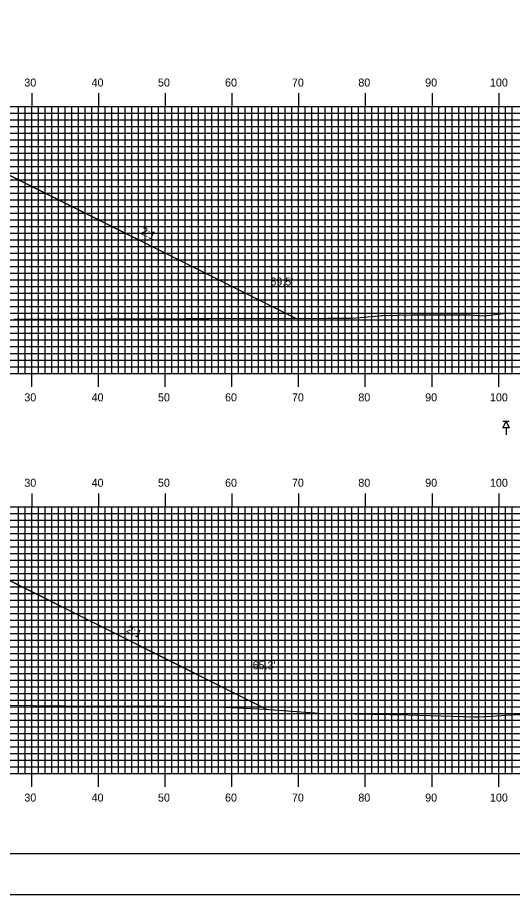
# Model space of a CAD drawing. Extents: x 1809013 to 1809356, y 442591 to 442811.
# Drawn here: x 1809206.2 to 1809280.4, y 442590.5 to 442722 of the extents above; entities that cross this region are included whole.
import ezdxf

# ---------------------------------------------------------------- set-up
doc = ezdxf.new("R2010")
doc.units = 0
for name, color, linetype in [('ANNOTATION', 7, 'Continuous'), ('BORDER', 7, 'Continuous'), ('BORING - NO REFUSAL', 7, 'Continuous'), ('D_Roadway_Centerline', 7, 'Continuous'), ('D_Roadway_SlopeLines', 7, 'Continuous'), ('D_Text_Standard', 7, 'Continuous'), ('H_V ANNOTATION', 7, 'Continuous'), ('MAJOR', 7, 'Continuous'), ('MINOR', 7, 'Continuous'), ('PLOT BOUNDARY', 7, 'Continuous'), ('S_Roadway_Centerline', 7, 'Continuous')]:
    doc.layers.add(name, color=color, linetype=linetype)

msp = doc.modelspace()

# ---------------------------------------------------------------- linework, layer by layer
at = {"layer": 'BORDER'}
msp.add_lwpolyline([(1809028.72, 442596.67), (1809348.72, 442596.67), (1809348.72, 442806.67), (1809028.72, 442806.67)], close=True, dxfattribs=at)
at = {"layer": 'BORING - NO REFUSAL'}
for p, q in [((1809279.9, 442661.47), (1809278.94, 442661.47)), ((1809279.42, 442660.51), (1809279.42, 442659.45))]:
    msp.add_line(p, q, dxfattribs=at)
msp.add_lwpolyline([(1809279.42, 442661.47), (1809279.9, 442660.51), (1809278.94, 442660.51)], close=True, dxfattribs=at)
at = {"layer": 'D_Roadway_Centerline'}
for points in [[(1809112.65, 442678.85), (1809150.57, 442697.82), (1809155.32, 442700.19), (1809158.32, 442700.31), (1809166.32, 442700.63), (1809178.32, 442700.87), (1809190.32, 442700.63), (1809198.32, 442700.31), (1809201.32, 442700.19), (1809206.07, 442697.82), (1809247.86, 442676.92)], [(1809117.27, 442620.41), (1809150.57, 442637.07), (1809155.32, 442639.44), (1809158.32, 442639.56), (1809166.32, 442639.88), (1809178.32, 442640.12), (1809190.32, 442639.88), (1809198.32, 442639.56), (1809201.32, 442639.44), (1809206.07, 442637.07), (1809243.63, 442618.29)]]:
    msp.add_lwpolyline(points, dxfattribs=at)
at = {"layer": 'D_Roadway_SlopeLines'}
for points in [[(1809201.32, 442700.19), (1809247.86, 442676.92)], [(1809201.32, 442639.44), (1809243.63, 442618.29)]]:
    msp.add_lwpolyline(points, dxfattribs=at)
at = {"layer": 'MAJOR'}
for p, q in [((1809208.32, 442710.67), (1809208.32, 442708.67)), ((1809218.32, 442710.67), (1809218.32, 442708.67)), ((1809228.32, 442710.67), (1809228.32, 442708.67)), ((1809238.32, 442710.67), (1809238.32, 442708.67)), ((1809248.32, 442710.67), (1809248.32, 442708.67)), ((1809258.32, 442710.67), (1809258.32, 442708.67)), ((1809268.32, 442710.67), (1809268.32, 442708.67)), ((1809278.32, 442710.67), (1809278.32, 442708.67)), ((1809038.32, 442708.67), (1809318.32, 442708.67)), ((1809038.32, 442708.67), (1809318.32, 442708.67)), ((1809208.32, 442668.67), (1809208.32, 442708.67)), ((1809218.32, 442668.67), (1809218.32, 442708.67)), ((1809228.32, 442668.67), (1809228.32, 442708.67)), ((1809238.32, 442668.67), (1809238.32, 442708.67)), ((1809248.32, 442668.67), (1809248.32, 442708.67)), ((1809258.32, 442668.67), (1809258.32, 442708.67)), ((1809268.32, 442668.67), (1809268.32, 442708.67)), ((1809278.32, 442668.67), (1809278.32, 442708.67)), ((1809038.32, 442703.67), (1809318.32, 442703.67)), ((1809038.32, 442698.67), (1809318.32, 442698.67)), ((1809038.32, 442693.67), (1809318.32, 442693.67)), ((1809038.32, 442688.67), (1809318.32, 442688.67)), ((1809038.32, 442683.67), (1809318.32, 442683.67)), ((1809038.32, 442678.67), (1809318.32, 442678.67)), ((1809038.32, 442673.67), (1809318.32, 442673.67)), ((1809038.32, 442668.67), (1809318.32, 442668.67)), ((1809038.32, 442668.67), (1809318.32, 442668.67)), ((1809208.32, 442666.66), (1809208.32, 442668.67)), ((1809218.32, 442666.66), (1809218.32, 442668.67)), ((1809228.32, 442666.66), (1809228.32, 442668.67)), ((1809238.32, 442666.66), (1809238.32, 442668.67)), ((1809248.32, 442666.66), (1809248.32, 442668.67)), ((1809258.32, 442666.66), (1809258.32, 442668.67)), ((1809268.32, 442666.66), (1809268.32, 442668.67)), ((1809278.32, 442666.66), (1809278.32, 442668.67)), ((1809208.32, 442650.67), (1809208.32, 442648.67)), ((1809218.32, 442650.67), (1809218.32, 442648.67)), ((1809228.32, 442650.67), (1809228.32, 442648.67)), ((1809238.32, 442650.67), (1809238.32, 442648.67)), ((1809248.32, 442650.67), (1809248.32, 442648.67)), ((1809258.32, 442650.67), (1809258.32, 442648.67)), ((1809268.32, 442650.67), (1809268.32, 442648.67)), ((1809278.32, 442650.67), (1809278.32, 442648.67)), ((1809038.32, 442648.67), (1809318.32, 442648.67)), ((1809038.32, 442648.67), (1809318.32, 442648.67)), ((1809208.32, 442608.67), (1809208.32, 442648.67)), ((1809218.32, 442608.67), (1809218.32, 442648.67)), ((1809228.32, 442608.67), (1809228.32, 442648.67)), ((1809238.32, 442608.67), (1809238.32, 442648.67)), ((1809248.32, 442608.67), (1809248.32, 442648.67)), ((1809258.32, 442608.67), (1809258.32, 442648.67)), ((1809268.32, 442608.67), (1809268.32, 442648.67)), ((1809278.32, 442608.67), (1809278.32, 442648.67)), ((1809038.32, 442643.67), (1809318.32, 442643.67)), ((1809038.32, 442638.67), (1809318.32, 442638.67)), ((1809038.32, 442633.67), (1809318.32, 442633.67)), ((1809038.32, 442628.67), (1809318.32, 442628.67)), ((1809038.32, 442623.67), (1809318.32, 442623.67)), ((1809038.32, 442618.67), (1809318.32, 442618.67)), ((1809038.32, 442613.67), (1809318.32, 442613.67)), ((1809038.32, 442608.67), (1809318.32, 442608.67)), ((1809038.32, 442608.67), (1809318.32, 442608.67)), ((1809208.32, 442606.66), (1809208.32, 442608.67)), ((1809218.32, 442606.66), (1809218.32, 442608.67)), ((1809228.32, 442606.66), (1809228.32, 442608.67)), ((1809238.32, 442606.66), (1809238.32, 442608.67)), ((1809248.32, 442606.66), (1809248.32, 442608.67)), ((1809258.32, 442606.66), (1809258.32, 442608.67)), ((1809268.32, 442606.66), (1809268.32, 442608.67)), ((1809278.32, 442606.66), (1809278.32, 442608.67))]:
    msp.add_line(p, q, dxfattribs=at)
at = {"layer": 'MINOR'}
for p, q in [((1809206.32, 442668.67), (1809206.32, 442708.67)), ((1809207.32, 442668.67), (1809207.32, 442708.67)), ((1809209.32, 442668.67), (1809209.32, 442708.67)), ((1809210.32, 442668.67), (1809210.32, 442708.67)), ((1809211.32, 442668.67), (1809211.32, 442708.67)), ((1809212.32, 442668.67), (1809212.32, 442708.67)), ((1809213.32, 442668.67), (1809213.32, 442708.67)), ((1809214.32, 442668.67), (1809214.32, 442708.67)), ((1809215.32, 442668.67), (1809215.32, 442708.67)), ((1809216.32, 442668.67), (1809216.32, 442708.67)), ((1809217.32, 442668.67), (1809217.32, 442708.67)), ((1809219.32, 442668.67), (1809219.32, 442708.67)), ((1809220.32, 442668.67), (1809220.32, 442708.67)), ((1809221.32, 442668.67), (1809221.32, 442708.67)), ((1809222.32, 442668.67), (1809222.32, 442708.67)), ((1809223.32, 442668.67), (1809223.32, 442708.67)), ((1809224.32, 442668.67), (1809224.32, 442708.67)), ((1809225.32, 442668.67), (1809225.32, 442708.67)), ((1809226.32, 442668.67), (1809226.32, 442708.67)), ((1809227.32, 442668.67), (1809227.32, 442708.67)), ((1809229.32, 442668.67), (1809229.32, 442708.67)), ((1809230.32, 442668.67), (1809230.32, 442708.67)), ((1809231.32, 442668.67), (1809231.32, 442708.67)), ((1809232.32, 442668.67), (1809232.32, 442708.67)), ((1809233.32, 442668.67), (1809233.32, 442708.67)), ((1809234.32, 442668.67), (1809234.32, 442708.67)), ((1809235.32, 442668.67), (1809235.32, 442708.67)), ((1809236.32, 442668.67), (1809236.32, 442708.67)), ((1809237.32, 442668.67), (1809237.32, 442708.67)), ((1809239.32, 442668.67), (1809239.32, 442708.67)), ((1809240.32, 442668.67), (1809240.32, 442708.67)), ((1809241.32, 442668.67), (1809241.32, 442708.67)), ((1809242.32, 442668.67), (1809242.32, 442708.67)), ((1809243.32, 442668.67), (1809243.32, 442708.67)), ((1809244.32, 442668.67), (1809244.32, 442708.67)), ((1809245.32, 442668.67), (1809245.32, 442708.67)), ((1809246.32, 442668.67), (1809246.32, 442708.67)), ((1809247.32, 442668.67), (1809247.32, 442708.67)), ((1809249.32, 442668.67), (1809249.32, 442708.67)), ((1809250.32, 442668.67), (1809250.32, 442708.67)), ((1809251.32, 442668.67), (1809251.32, 442708.67)), ((1809252.32, 442668.67), (1809252.32, 442708.67)), ((1809253.32, 442668.67), (1809253.32, 442708.67)), ((1809254.32, 442668.67), (1809254.32, 442708.67)), ((1809255.32, 442668.67), (1809255.32, 442708.67)), ((1809256.32, 442668.67), (1809256.32, 442708.67)), ((1809257.32, 442668.67), (1809257.32, 442708.67)), ((1809259.32, 442668.67), (1809259.32, 442708.67)), ((1809260.32, 442668.67), (1809260.32, 442708.67)), ((1809261.32, 442668.67), (1809261.32, 442708.67)), ((1809262.32, 442668.67), (1809262.32, 442708.67)), ((1809263.32, 442668.67), (1809263.32, 442708.67)), ((1809264.32, 442668.67), (1809264.32, 442708.67)), ((1809265.32, 442668.67), (1809265.32, 442708.67)), ((1809266.32, 442668.67), (1809266.32, 442708.67)), ((1809267.32, 442668.67), (1809267.32, 442708.67)), ((1809269.32, 442668.67), (1809269.32, 442708.67)), ((1809270.32, 442668.67), (1809270.32, 442708.67)), ((1809271.32, 442668.67), (1809271.32, 442708.67)), ((1809272.32, 442668.67), (1809272.32, 442708.67)), ((1809273.32, 442668.67), (1809273.32, 442708.67)), ((1809274.32, 442668.67), (1809274.32, 442708.67)), ((1809275.32, 442668.67), (1809275.32, 442708.67)), ((1809276.32, 442668.67), (1809276.32, 442708.67)), ((1809277.32, 442668.67), (1809277.32, 442708.67)), ((1809279.32, 442668.67), (1809279.32, 442708.67)), ((1809280.32, 442668.67), (1809280.32, 442708.67)), ((1809038.32, 442707.67), (1809318.32, 442707.67)), ((1809038.32, 442706.67), (1809318.32, 442706.67)), ((1809038.32, 442705.67), (1809318.32, 442705.67)), ((1809038.32, 442704.67), (1809318.32, 442704.67)), ((1809038.32, 442702.67), (1809318.32, 442702.67)), ((1809038.32, 442701.67), (1809318.32, 442701.67)), ((1809038.32, 442700.67), (1809318.32, 442700.67)), ((1809038.32, 442699.67), (1809318.32, 442699.67)), ((1809038.32, 442697.67), (1809318.32, 442697.67)), ((1809038.32, 442696.67), (1809318.32, 442696.67)), ((1809038.32, 442695.67), (1809318.32, 442695.67)), ((1809038.32, 442694.67), (1809318.32, 442694.67)), ((1809038.32, 442692.67), (1809318.32, 442692.67)), ((1809038.32, 442691.67), (1809318.32, 442691.67)), ((1809038.32, 442690.67), (1809318.32, 442690.67)), ((1809038.32, 442689.67), (1809318.32, 442689.67)), ((1809038.32, 442687.67), (1809318.32, 442687.67)), ((1809038.32, 442686.67), (1809318.32, 442686.67)), ((1809038.32, 442685.67), (1809318.32, 442685.67)), ((1809038.32, 442684.67), (1809318.32, 442684.67)), ((1809038.32, 442682.67), (1809318.32, 442682.67)), ((1809038.32, 442681.67), (1809318.32, 442681.67)), ((1809038.32, 442680.67), (1809318.32, 442680.67)), ((1809038.32, 442679.67), (1809318.32, 442679.67)), ((1809038.32, 442677.67), (1809318.32, 442677.67)), ((1809038.32, 442676.67), (1809318.32, 442676.67)), ((1809038.32, 442675.67), (1809318.32, 442675.67)), ((1809038.32, 442674.67), (1809318.32, 442674.67)), ((1809038.32, 442672.67), (1809318.32, 442672.67)), ((1809038.32, 442671.67), (1809318.32, 442671.67)), ((1809038.32, 442670.67), (1809318.32, 442670.67)), ((1809038.32, 442669.67), (1809318.32, 442669.67)), ((1809038.32, 442647.67), (1809318.32, 442647.67)), ((1809206.32, 442608.67), (1809206.32, 442648.67)), ((1809207.32, 442608.67), (1809207.32, 442648.67)), ((1809209.32, 442608.67), (1809209.32, 442648.67)), ((1809210.32, 442608.67), (1809210.32, 442648.67)), ((1809211.32, 442608.67), (1809211.32, 442648.67)), ((1809212.32, 442608.67), (1809212.32, 442648.67)), ((1809213.32, 442608.67), (1809213.32, 442648.67)), ((1809214.32, 442608.67), (1809214.32, 442648.67)), ((1809215.32, 442608.67), (1809215.32, 442648.67)), ((1809216.32, 442608.67), (1809216.32, 442648.67)), ((1809217.32, 442608.67), (1809217.32, 442648.67)), ((1809219.32, 442608.67), (1809219.32, 442648.67)), ((1809220.32, 442608.67), (1809220.32, 442648.67)), ((1809221.32, 442608.67), (1809221.32, 442648.67)), ((1809222.32, 442608.67), (1809222.32, 442648.67)), ((1809223.32, 442608.67), (1809223.32, 442648.67)), ((1809224.32, 442608.67), (1809224.32, 442648.67)), ((1809225.32, 442608.67), (1809225.32, 442648.67)), ((1809226.32, 442608.67), (1809226.32, 442648.67)), ((1809227.32, 442608.67), (1809227.32, 442648.67)), ((1809229.32, 442608.67), (1809229.32, 442648.67)), ((1809230.32, 442608.67), (1809230.32, 442648.67)), ((1809231.32, 442608.67), (1809231.32, 442648.67)), ((1809232.32, 442608.67), (1809232.32, 442648.67)), ((1809233.32, 442608.67), (1809233.32, 442648.67)), ((1809234.32, 442608.67), (1809234.32, 442648.67)), ((1809235.32, 442608.67), (1809235.32, 442648.67)), ((1809236.32, 442608.67), (1809236.32, 442648.67)), ((1809237.32, 442608.67), (1809237.32, 442648.67)), ((1809239.32, 442608.67), (1809239.32, 442648.67)), ((1809240.32, 442608.67), (1809240.32, 442648.67)), ((1809241.32, 442608.67), (1809241.32, 442648.67)), ((1809242.32, 442608.67), (1809242.32, 442648.67)), ((1809243.32, 442608.67), (1809243.32, 442648.67)), ((1809244.32, 442608.67), (1809244.32, 442648.67)), ((1809245.32, 442608.67), (1809245.32, 442648.67)), ((1809246.32, 442608.67), (1809246.32, 442648.67)), ((1809247.32, 442608.67), (1809247.32, 442648.67)), ((1809249.32, 442608.67), (1809249.32, 442648.67)), ((1809250.32, 442608.67), (1809250.32, 442648.67)), ((1809251.32, 442608.67), (1809251.32, 442648.67)), ((1809252.32, 442608.67), (1809252.32, 442648.67)), ((1809253.32, 442608.67), (1809253.32, 442648.67)), ((1809254.32, 442608.67), (1809254.32, 442648.67)), ((1809255.32, 442608.67), (1809255.32, 442648.67)), ((1809256.32, 442608.67), (1809256.32, 442648.67)), ((1809257.32, 442608.67), (1809257.32, 442648.67)), ((1809259.32, 442608.67), (1809259.32, 442648.67)), ((1809260.32, 442608.67), (1809260.32, 442648.67)), ((1809261.32, 442608.67), (1809261.32, 442648.67)), ((1809262.32, 442608.67), (1809262.32, 442648.67)), ((1809263.32, 442608.67), (1809263.32, 442648.67)), ((1809264.32, 442608.67), (1809264.32, 442648.67)), ((1809265.32, 442608.67), (1809265.32, 442648.67)), ((1809266.32, 442608.67), (1809266.32, 442648.67)), ((1809267.32, 442608.67), (1809267.32, 442648.67)), ((1809269.32, 442608.67), (1809269.32, 442648.67)), ((1809270.32, 442608.67), (1809270.32, 442648.67)), ((1809271.32, 442608.67), (1809271.32, 442648.67)), ((1809272.32, 442608.67), (1809272.32, 442648.67)), ((1809273.32, 442608.67), (1809273.32, 442648.67)), ((1809274.32, 442608.67), (1809274.32, 442648.67)), ((1809275.32, 442608.67), (1809275.32, 442648.67)), ((1809276.32, 442608.67), (1809276.32, 442648.67)), ((1809277.32, 442608.67), (1809277.32, 442648.67)), ((1809279.32, 442608.67), (1809279.32, 442648.67)), ((1809280.32, 442608.67), (1809280.32, 442648.67)), ((1809038.32, 442646.67), (1809318.32, 442646.67)), ((1809038.32, 442645.67), (1809318.32, 442645.67)), ((1809038.32, 442644.67), (1809318.32, 442644.67)), ((1809038.32, 442642.67), (1809318.32, 442642.67)), ((1809038.32, 442641.67), (1809318.32, 442641.67)), ((1809038.32, 442640.67), (1809318.32, 442640.67)), ((1809038.32, 442639.67), (1809318.32, 442639.67)), ((1809038.32, 442637.67), (1809318.32, 442637.67)), ((1809038.32, 442636.67), (1809318.32, 442636.67)), ((1809038.32, 442635.67), (1809318.32, 442635.67)), ((1809038.32, 442634.67), (1809318.32, 442634.67)), ((1809038.32, 442632.67), (1809318.32, 442632.67)), ((1809038.32, 442631.67), (1809318.32, 442631.67)), ((1809038.32, 442630.67), (1809318.32, 442630.67)), ((1809038.32, 442629.67), (1809318.32, 442629.67)), ((1809038.32, 442627.67), (1809318.32, 442627.67)), ((1809038.32, 442626.67), (1809318.32, 442626.67)), ((1809038.32, 442625.67), (1809318.32, 442625.67)), ((1809038.32, 442624.67), (1809318.32, 442624.67)), ((1809038.32, 442622.67), (1809318.32, 442622.67)), ((1809038.32, 442621.67), (1809318.32, 442621.67)), ((1809038.32, 442620.67), (1809318.32, 442620.67)), ((1809038.32, 442619.67), (1809318.32, 442619.67)), ((1809038.32, 442617.67), (1809318.32, 442617.67)), ((1809038.32, 442616.67), (1809318.32, 442616.67)), ((1809038.32, 442615.67), (1809318.32, 442615.67)), ((1809038.32, 442614.67), (1809318.32, 442614.67)), ((1809038.32, 442612.67), (1809318.32, 442612.67)), ((1809038.32, 442611.67), (1809318.32, 442611.67)), ((1809038.32, 442610.67), (1809318.32, 442610.67)), ((1809038.32, 442609.67), (1809318.32, 442609.67))]:
    msp.add_line(p, q, dxfattribs=at)
at = {"layer": 'PLOT BOUNDARY'}
msp.add_lwpolyline([(1809012.54, 442590.55), (1809352.54, 442590.55), (1809352.54, 442810.55), (1809012.54, 442810.55)], close=True, dxfattribs=at)
at = {"layer": 'S_Roadway_Centerline'}
for points in [[(1809205.65, 442676.78), (1809207.67, 442676.78), (1809219.35, 442676.83), (1809222.57, 442676.83), (1809231.48, 442676.89), (1809234.9, 442676.9), (1809252.73, 442676.93), (1809252.96, 442676.93), (1809253.24, 442676.93), (1809256.39, 442676.94), (1809260.9, 442677.36), (1809265.23, 442677.45), (1809274.04, 442677.45), (1809276.16, 442677.27), (1809279.43, 442677.68), (1809289.04, 442677.69), (1809293.8, 442677.99), (1809300.57, 442678.12), (1809308.92, 442678), (1809318.32, 442678.09)], [(1809193.97, 442619.02), (1809218.3, 442618.76), (1809228.11, 442618.77), (1809236.02, 442618.69), (1809243.32, 442618.31), (1809251.38, 442617.73), (1809264.7, 442617.5), (1809274.69, 442617.17), (1809275.36, 442617.17), (1809276.46, 442617.23), (1809280.18, 442617.49), (1809282.88, 442617.51), (1809283.8, 442617.55), (1809291.27, 442617.59), (1809303.06, 442617.71), (1809308.91, 442617.68), (1809309.81, 442617.36), (1809313.26, 442616.98), (1809314.08, 442617.1), (1809318.32, 442617.11)]]:
    msp.add_lwpolyline(points, dxfattribs=at)

# ---------------------------------------------------------------- texts
at = {"layer": 'ANNOTATION'}
for p in [(1809224.53, 442689.63), (1809222.41, 442629.93)]:
    msp.add_text('2:1', height=1.2, rotation=333.4349, dxfattribs=at).set_placement(p)
at = {"layer": 'D_Text_Standard'}
for s, p in [("69.5'", (1809244.1, 442681.83)), ("65.3'", (1809241.44, 442624.31))]:
    msp.add_text(s, height=1.2, dxfattribs=at).set_placement(p)
at = {"layer": 'H_V ANNOTATION'}
for s, p in [('30', (1809207.22, 442711.67)), ('40', (1809217.3, 442711.67)), ('50', (1809227.25, 442711.67)), ('60', (1809237.3, 442711.67)), ('70', (1809247.33, 442711.67)), ('80', (1809257.28, 442711.67)), ('90', (1809267.3, 442711.67)), ('100', (1809277.01, 442711.67)), ('30', (1809207.22, 442664.47)), ('40', (1809217.3, 442664.47)), ('50', (1809227.25, 442664.47)), ('60', (1809237.3, 442664.47)), ('70', (1809247.33, 442664.47)), ('80', (1809257.28, 442664.47)), ('90', (1809267.3, 442664.47)), ('100', (1809277.01, 442664.47)), ('30', (1809207.22, 442651.67)), ('40', (1809217.3, 442651.67)), ('50', (1809227.25, 442651.67)), ('60', (1809237.3, 442651.67)), ('70', (1809247.33, 442651.67)), ('80', (1809257.28, 442651.67)), ('90', (1809267.3, 442651.67)), ('100', (1809277.01, 442651.67)), ('30', (1809207.22, 442604.47)), ('40', (1809217.3, 442604.47)), ('50', (1809227.25, 442604.47)), ('60', (1809237.3, 442604.47)), ('70', (1809247.33, 442604.47)), ('80', (1809257.28, 442604.47)), ('90', (1809267.3, 442604.47)), ('100', (1809277.01, 442604.47))]:
    msp.add_text(s, height=1.2, dxfattribs=at).set_placement(p)

doc.saveas('drawing.dxf')
